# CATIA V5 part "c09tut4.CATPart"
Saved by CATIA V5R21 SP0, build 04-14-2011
Part number: Part1
Bounding box of the stored display mesh (mm): x -112.5 to 112.5, y -202.31 to 80, z -202.31 to 85
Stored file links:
  D:\CATIA V5R21 E-RESOURCES\CATIA-V5R21\catia-v5r21-Tut\c09-catia-v5r21-tut\c09_catia_v5r21-tut04.CATPart
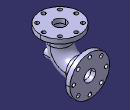
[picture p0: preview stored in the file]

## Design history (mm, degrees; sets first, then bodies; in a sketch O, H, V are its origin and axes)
Body1 (main body)
  Sketch1 on yz-plane, origin (0, 0, 0), H (0, 1, 0), V (0, 0, 1)
    point P1 (-90, 60)
    line L1 (-90, 60) -> (-90, 0)
    point P3 (0, -90)
    line L2 (0, -90) -> (55, -90)
    point P4 (55, -90)
    arc A1 centre (0, 0) radius 90 from (0, -90) to (-90, 0) cw
    point P5 (0, 0)
    point P6 (-90, 0)
    radius A1 = 90
    distance P1 L2 = 150
    distance P4 L1 = 145
    vertical: L1 V
    coincidence: P3 V, A1 P6, P6 L1, O P5
    horizontal: L2 H
    tangency: A1 L1, A1 L2
  Plane1: type Normal, Curve Sketch1, RefPoint Sketch1.P4
  Sketch2 on Plane1, origin (0, 55, 0), H (-1, 0, 0), V (0, 0, 1)
    circle A1 centre (0, -90) radius 48.5
    point P1 (0, -90)
    radius A1 = 48.5
    coincidence: P1 V
  Rib1: profile Sketch2, centre curve Sketch1, thin wall 16
  Sketch3 on face of Rib1, origin (0, 0, 60), H (1, 0, 0), V (0, 1, 0)
    circle A1 centre (0, -90) radius 112.5
    point P1 (0, -90)
    reference projected circle E1 centre (0, -90) radius 40.5 from edge [face of Rib1 | face of Rib1]
    radius A1 = 112.5
    coincidence: P1 V
    concentricity: E1 A1
  Pad1: profile Sketch3, direction (0, 0, 1), length 25
  Sketch4 on face of Rib1, origin (0, 55, 0), H (-1, 0, 0), V (0, 0, 1)
    circle A1 centre (0, -90) radius 112.5
    point P1 (0, -90)
    reference projected circle E1 centre (0, -90) radius 40.5 from edge [face of Rib1 | face of Rib1]
    radius A1 = 112.5
    coincidence: P1 V
    concentricity: E1 A1
  Pad2: profile Sketch4, direction (0, 1, 0), length 25
  Sketch5 on end face of Pad2, origin (0, 80, 0), H (-1, 0, 0), V (0, 0, 1)
    circle A1 centre (0, -90) radius 32.5
    point P1 (0, -90)
    reference projected circle E1 centre (0, -90) radius 112.5 from edge [face of Pad2 from Sketch4.A1 | end face of Pad2]
    radius A1 = 32.5
    coincidence: P1 V
    concentricity: E1 A1
  Pocket1: profile Sketch5, direction (0, -1, 0), through (limit type 6)
  Sketch6 on end face of Pad1, origin (0, 0, 85), H (1, 0, 0), V (0, 1, 0)
    circle A1 centre (0, -90) radius 32.5
    point P1 (0, -90)
    point P2 (0, -122.5)
    reference projected circle E1 centre (0, -90) radius 112.5 from edge [face of Pad1 from Sketch3.A1 | end face of Pad1]
    radius A1 = 32.5
    coincidence: P1 V, A1 P2, P2 V
    concentricity: E1 A1
  Pocket2: profile Sketch6, direction (0, 0, -1), through (limit type 6)
  Sketch7 on end face of Pad1, origin (0, 0, 85), H (1, 0, 0), V (0, 1, 0)
    circle A1 centre (0, -182.5) radius 10.25
    radius A1 = 10.25
  Pocket3: profile Sketch7, direction (0, 0, -1), through (limit type 3)
  CircPattern1: of Pocket3, instances 8, angular step 45, axis from end face of Pad1
  Sketch8 on end face of Pad2, origin (0, 80, 0), H (-1, 0, 0), V (0, 0, 1)
    circle A1 centre (0, -182.5) radius 10.25
    radius A1 = 10.25
  Pocket4: profile Sketch8, direction (0, -1, 0), through (limit type 3)
  CircPattern2: of Pocket4, instances 8, angular step 45, axis from end face of Pad2
  Plane2: type Offset, RefPlane end face of Pad2, Offset 240
  Sketch9 on Plane2, origin (0, -160, 0), H (1, 0, 0), V (0, 0, 1)
    circle A1 centre (0, -90) radius 25
    point P1 (0, -90)
    point P2 (0, -115)
    reference projected circle E1 centre (0, -90) radius 112.5 from edge [start face of Pad2 | face of Pad2 from Sketch4.A1]
    radius A1 = 25
    coincidence: P1 V, A1 P2, P2 V
    concentricity: E1 A1
  Pad3: profile Sketch9, direction (0, -1, 0), up to the existing solid (limit type 2)
  Sketch10 on start face of Pad3, origin (0, -160, 0), H (1, 0, 0), V (0, 0, 1)
    circle A1 centre (0, -90) radius 10
    point P1 (0, -90)
    reference projected circle E1 centre (0, -90) radius 25 from edge [face of Pad3 from Sketch9.A1 | start face of Pad3]
    radius A1 = 10
    coincidence: P1 V
    concentricity: E1 A1
  Pocket5: profile Sketch10, direction (0, 1, 0), length 28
